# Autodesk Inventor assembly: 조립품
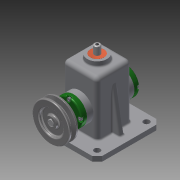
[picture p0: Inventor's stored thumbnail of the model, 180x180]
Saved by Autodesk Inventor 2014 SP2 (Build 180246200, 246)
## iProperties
Created: 2016-02
Part Number: 조립품
Document SubType Name: Assembly
Designer: 1sil_ho3333
Author: 1sil_ho3333
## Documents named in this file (16)
- C:\Users\1sil_ho3333\Desktop\460212V1012\조립품.iam
- C:\Users\1sil_ho3333\Desktop\460212V1012\본체.ipt
- C:\Users\1sil_ho3333\Desktop\460212V1012\편심축.ipt
- C:\Users\1sil_ho3333\Desktop\460212V1012\슬라이드.ipt
- C:\Users\1sil_ho3333\Desktop\460212V1012\링크.ipt
- C:\Users\1sil_ho3333\Desktop\460212V1012\핀 5 x 18.ipt
- C:\Users\1sil_ho3333\Desktop\460212V1012\고정핀 1.2 x 10.ipt
- C:\Users\1sil_ho3333\Desktop\460212V1012\뒤커버.ipt
- C:\Users\1sil_ho3333\Desktop\460212V1012\베어링 12 x 32 x 10.ipt
- C:\Users\1sil_ho3333\Desktop\460212V1012\앞커버.ipt
- C:\Users\1sil_ho3333\Desktop\460212V1012\오일실 12 25 7.ipt
- C:\Users\1sil_ho3333\Desktop\460212V1012\볼트 M4 x 12.ipt
- C:\Users\1sil_ho3333\Desktop\460212V1012\키 4 x 4 x 10.ipt
- C:\Users\1sil_ho3333\Desktop\460212V1012\V벨트풀리.ipt
- C:\Users\1sil_ho3333\Desktop\460212V1012\멈춤나사 M3x8.ipt
- C:\Users\1sil_ho3333\Desktop\460212V1012\부시.ipt
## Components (11 placed, 4 different names)
1. 핀 5 x 18:1 — 각도:7
2. 고정핀 1.2 x 10:1 — 각도:7
3. V벨트풀리:1 — 각도:5, 각도:6
4. ISO 4762 M4 x 12:1 — 각도:2
5. ISO 4762 M4 x 12:2
6. ISO 4762 M4 x 12:3
7. ISO 4762 M4 x 12:4
8. ISO 4762 M4 x 12:5 — 각도:3
9. ISO 4762 M4 x 12:6
10. ISO 4762 M4 x 12:7
11. ISO 4762 M4 x 12:8
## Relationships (5: Angle 5)
- 각도:2 [Angle]: ISO 4762 M4 x 12:1
- 각도:3 [Angle]: ISO 4762 M4 x 12:5
- 각도:5 [Angle]: V벨트풀리:1
- 각도:6 [Angle]: V벨트풀리:1
- 각도:7 [Angle]: 핀 5 x 18:1 ↔ 고정핀 1.2 x 10:1
